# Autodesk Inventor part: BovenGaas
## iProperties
Created: 2010-03
Part Number: BovenGaas
Document SubType Name: Modeling
Designer: Ferry
Density: 1 g/cm^3
Author: Ferry
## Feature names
1. Extrusion1
